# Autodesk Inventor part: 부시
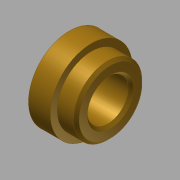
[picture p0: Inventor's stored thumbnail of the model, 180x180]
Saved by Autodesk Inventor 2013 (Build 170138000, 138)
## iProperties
Created: 2016-05
Part Number: 부시
Document SubType Name: Modeling
Designer: mduedu
Density: 7.86 g/cm^3
Material: 강철, 연강
Author: mduedu
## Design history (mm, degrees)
sketch "스케치1"
  geometry: L1 (0, 0)-(15, 0); L2 (0, 7.5)-(15, 7.5); L3 (15, 7.5)-(15, 12.5); L4 (15, 12.5)-(8, 12.5); L5 (8, 12.5)-(8, 15); L6 (8, 15)-(0, 15); L7 (0, 15)-(0, 7.5)
  constraints: 14 end point, 4 parallel, 2 vertical alignment, 1 horizontal, 1 perpendicular, 1 vertical
  dimensions: "d0" = 15 distance of L1.start L1.end; "d1" = 15 diameter of L2 L1; "d2" = 25 diameter of L4 L1; "d3" = 8 distance of L5.end L6.end; "d4" = 30 diameter of L6 L1
revolve "회전1" sketch "스케치1" stored, may be unused: angle "d5" = 90 deg
chamfer "모따기1" distance "d6" = 1; stored, may be unused: second distance "d7" = 2, angle "d8" = 45 deg
chamfer "모따기2" distance "d9" = 1; stored, may be unused: second distance "d10" = 2, angle "d11" = 45 deg
node "솔리드1"
